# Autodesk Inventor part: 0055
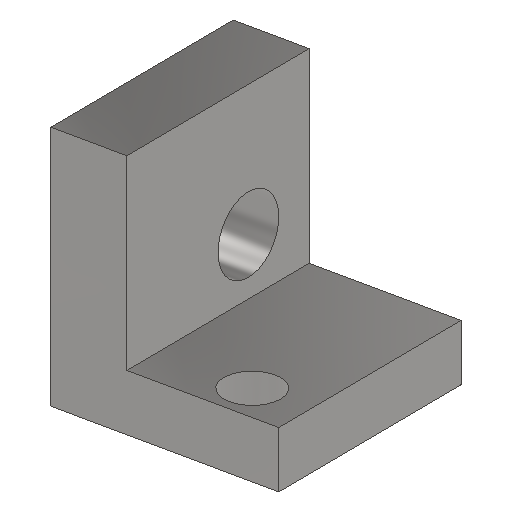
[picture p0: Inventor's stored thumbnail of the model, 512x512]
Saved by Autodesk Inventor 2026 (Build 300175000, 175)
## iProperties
Created: 2004-09
Part Number: 0055
Document SubType Name: Modeling
Designer: Lars Bertram Pedersen
Manufacturer: Standard
Standards Organization: Custom
Material: Steel, Mild
Density: 7.85 g/cm^3
Appearance: Semi-Polished
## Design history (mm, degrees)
sketch "Sketch1"
  geometry: L1 (0, 0)-(60, 0); L2 (60, 0)-(60, 15); L3 (60, 15)-(20, 15); L4 (20, 15)-(20, 65); L5 (20, 65)-(0, 65); L6 (0, 65)-(0, 0); 1 further point
  constraints: 12 end point, 3 perpendicular, 2 parallel, 1 coincident, 1 horizontal
  dimensions: "d0" = 60 distance of L1.start L1.end; "d1" = 15 distance of L1.end L2.end; "d2" = 50 distance of L3.end L4.end; "d3" = 20 distance of L4.end L5.end
extrude "Extrusion1" new body sketch "Sketch1" distance "d4" = 60; taper "d5" = 0 deg
sketch "Sketch4"
  geometry: L1 (-60, 50)-(-60, 0) reference; L2 (0, 0)-(-60, 0) reference; C1 r 10 at (-20, 15)
  constraints: 1 centre point
  dimensions: "d19" = 20 diameter of C1; "d20" = 15 distance from line of L2 C1.centre; "d21" = 40 distance from line of L1 C1.centre
extrude "Extrusion5" cut sketch "Sketch4" extent not by distance; stored distance "d22" = 10; taper "d23" = 0 deg
body "Solid1"
sketch "Sketch2"
  geometry: L1 (0, -60)-(40, -60) reference; L2 (0, 0)-(0, -60) reference; C1 r 7.5 at (25, -50)
  constraints: 1 centre point
  dimensions: "d12" = 15 diameter of C1; "d13" = 10 distance from line of C1.centre L1; "d14" = 25 distance from line of C1.centre L2
extrude "Extrusion2" cut sketch "Sketch2" extent not by distance; stored distance "d17" = 10; taper "d18" = 0 deg
